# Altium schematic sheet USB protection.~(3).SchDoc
size A3; SheetNumber: 7; SheetTotal: 7
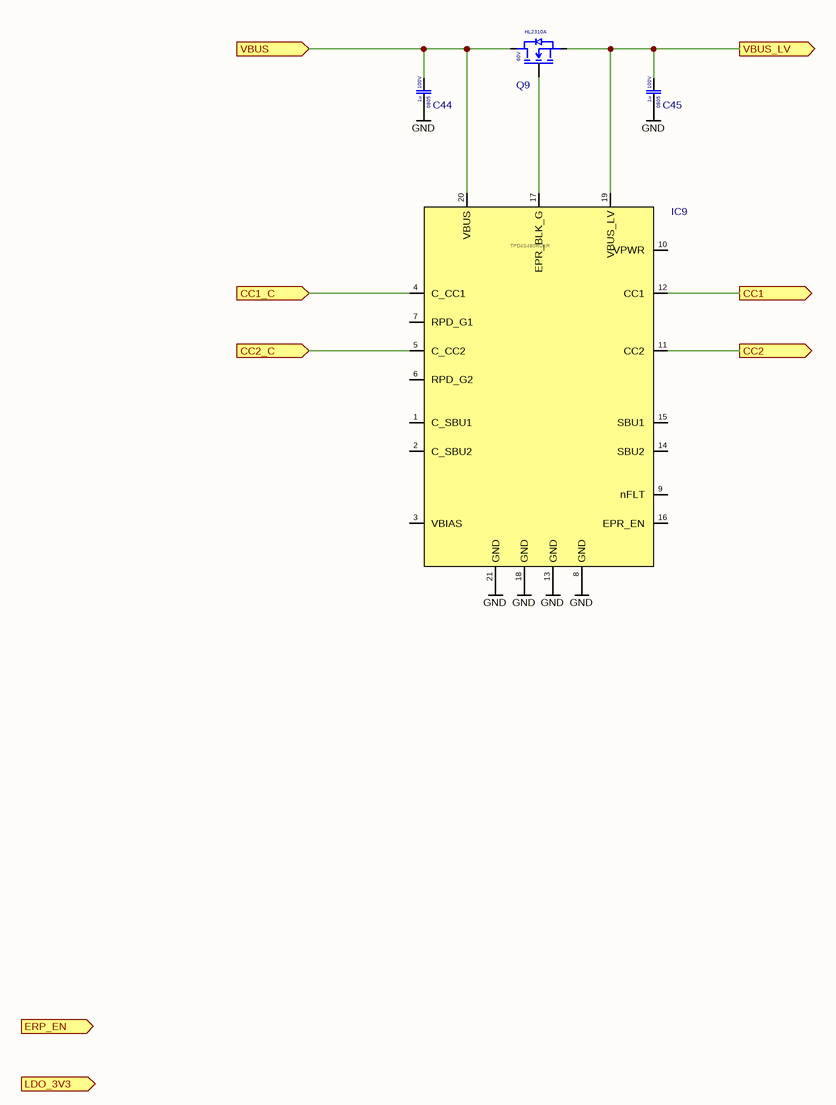
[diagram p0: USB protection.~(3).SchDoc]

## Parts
C44  Voltage Rating: 100V  Case Code (Imperial): 0805  Capacitance: 1u  [Cap_0805]  (hidden comment: CC0805KKX7R0BB105)
C45  Voltage Rating: 100V  Case Code (Imperial): 0805  Capacitance: 1u  [Cap_0805]  (hidden comment: CC0805KKX7R0BB105)
IC9  TPD4S480RUKR  [WQFN (20)]
Q9  Voltage: 60V  [SOT-23 GSD]  (hidden comment: HL2310A)

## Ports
CC1 (out, see Arhitecture[3B], USB PD[3C]), CC1_C (in, see Arhitecture[2B]), CC2 (out, see Arhitecture[3B], USB PD[3C]), CC2_C (in, see Arhitecture[2B]), ERP_EN (out, see Arhitecture[3B], USB PD[5B]), LDO_3V3 (in, see Arhitecture[3B], USB PD[3C]), VBUS (in, see Arhitecture[2B], Power path switch[3B]), VBUS_LV (out, see Arhitecture[3B], USB PD[3B])

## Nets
GND: C44.1 C45.1 IC9.8(GND) IC9.13(GND) IC9.18(GND) IC9.21(GND)
CC1: IC9.12(CC1) ; port CC1
CC1_C: IC9.4(C_CC1) ; port CC1_C
CC2: IC9.11(CC2) ; port CC2
CC2_C: IC9.5(C_CC2) ; port CC2_C
VBUS: C44.2 IC9.20(VBUS) Q9.D ; port VBUS
VBUS_LV: C45.2 IC9.19(VBUS_LV) Q9.S ; port VBUS_LV
NetIC9_17: IC9.17(EPR_BLK_G) Q9.G

Not connected (* = marked no-connect by the designer): IC9 1(C_SBU1) 2(C_SBU2) 3(VBIAS) 6(RPD_G2) 7(RPD_G1) 9(nFLT) 10(VPWR) 14(SBU2) 15(SBU1) 16(EPR_EN)

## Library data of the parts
C44 C45 = CC0805KKX7R0BB105: Cap 1uF 100V 0805 X7R; Manufacturer: Yageo
IC9 = TPD4S480RUKR: USB PD protection IC; Manufacturer: Texas Instruments
Q9 = HL2310A: nMOS 60V 3A SOT-23; Manufacturer: hongjiacheng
